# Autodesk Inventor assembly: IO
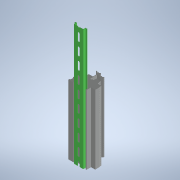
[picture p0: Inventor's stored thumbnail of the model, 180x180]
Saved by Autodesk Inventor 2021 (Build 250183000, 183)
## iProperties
Category: PARTsolutions
Created: 2026-07
Part Number: IO
Catalog Web Link: www.3dfindit.com
Description: -
Document SubType Name: Assembly
Designer: psAdmin
Mass: 418.05 g
Surface Area: 2883.22 cm^2
Volume: 438.721 cm^3
Density: 0.952883 g/cm^3
Title: IO
Author: Cadenas PARTsolutions
ARTICLENO: IO
BOMINFO: IO
CREATOR: CADENAS GmbH
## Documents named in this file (3)
- e:\temp\worker_COMMON_151\temp\tmp_1876_0_ENb2k\format_0\IO.iam
- e:\temp\worker_COMMON_151\temp\tmp_1876_0_ENb2k\format_0\WAGO_210-112350.ipt
- e:\temp\worker_COMMON_151\temp\tmp_1876_0_ENb2k\format_0\280-519_LO.ipt
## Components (41 placed, 2 different names)
1. WAGO_210-112350:1
2. 280-519_LO:1
3. 280-519_LO:2
4. 280-519_LO:3
5. 280-519_LO:4
6. 280-519_LO:5
7. 280-519_LO:6
8. 280-519_LO:7
9. 280-519_LO:8
10. 280-519_LO:9
11. 280-519_LO:10
12. 280-519_LO:11
13. 280-519_LO:12
14. 280-519_LO:13
15. 280-519_LO:14
16. 280-519_LO:15
17. 280-519_LO:16
18. 280-519_LO:17
19. 280-519_LO:18
20. 280-519_LO:19
21. 280-519_LO:20
22. 280-519_LO:21
23. 280-519_LO:22
24. 280-519_LO:23
25. 280-519_LO:24
26. 280-519_LO:25
27. 280-519_LO:26
28. 280-519_LO:27
29. 280-519_LO:28
30. 280-519_LO:29
31. 280-519_LO:30
32. 280-519_LO:31
33. 280-519_LO:32
34. 280-519_LO:33
35. 280-519_LO:34
36. 280-519_LO:35
37. 280-519_LO:36
38. 280-519_LO:37
39. 280-519_LO:38
40. 280-519_LO:39
41. 280-519_LO:40
